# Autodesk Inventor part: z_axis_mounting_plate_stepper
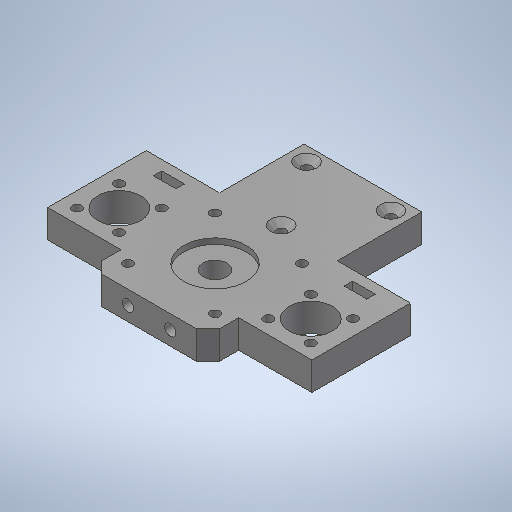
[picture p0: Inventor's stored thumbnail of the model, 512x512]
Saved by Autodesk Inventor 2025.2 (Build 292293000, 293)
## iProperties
Created: 2025-04
Part Number: z_axis_mounting_plate_stepper
Material: 1.0037 S235JR
Document SubType Name: Modeling
Designer: BennF
Density: 7.85 g/cm^3
Appearance: Stahl
Author: BennF
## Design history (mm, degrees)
sketch "Sketch2"
  geometry: L1 (20.9, 75.9)-(-20.9, 75.9); L2 (-20.9, 75.9)-(-20.9, 35.9); L3 (-20.9, 35.9)-(-46.9, 35.9); L4 (-46.9, 35.9)-(-46.9, 10.9); L5 (46.9, 10.9)-(46.9, 35.9); L6 (46.9, 35.9)-(20.9, 35.9); L7 (20.9, 35.9)-(20.9, 75.9); L8 (-20.9, 10.9)-(-20.9, 0); L9 (-20.9, 0)-(20.9, 0); L10 (20.9, 0)-(20.9, 10.9); L11 (-46.9, 10.9)-(-20.9, 10.9); L12 (20.9, 10.9)-(46.9, 10.9); 4 further points
  constraints: 25 end point, 11 perpendicular, 3 midpoint, 2 point on line, 2 vertical alignment, 1 coincident, 1 collinear, 1 horizontal, 1 horizontal alignment, 1 vertical
  dimensions: "d0" = 41.8 distance of L1.start L1.end; "d3" = 93.8 distance of L4.end L5.start (computed from d0); "d34" = 40 distance of L6.end L1.start; "d35" = 10.9 distance of L9.end L10.end; "d36" = 52.5 distance from line of point (46.9, 23.4) L1 (derived); "d37" = 25 distance of L3.end L4.end
extrude "Extrusion1" new body sketch "Sketch2" distance "d4" = 10; taper "d5" = 0 deg
sketch "Sketch3"
  geometry: L1 (-15.5, 38.9)-(15.5, 38.9); L2 (15.5, 38.9)-(15.5, 7.9); L3 (15.5, 7.9)-(-15.5, 7.9); L4 (-15.5, 7.9)-(-15.5, 38.9); L5 (46.9, 35.9)-(46.9, 10.9) reference; 6 further points
  constraints: 8 end point, 3 horizontal alignment, 3 midpoint, 2 parallel, 2 perpendicular, 2 vertical alignment, 1 horizontal
  dimensions: "d13" = 31 distance of L1.start L1.end
hole "Hole1" sketch "Sketch3" at (-15.5, 7.9), (-15.5, 38.9), (15.5, 38.9), (15.5, 7.9) diameter "d6" = 3.4; stored, may be unused: countersink angle "d10" = 90 deg, drill point angle "d12" = 118 deg; dims "d7" = 6, "d8" = 7.5, "d9" = 2, "d11" = 8
sketch "Sketch4"
  geometry: L1 (46.9, -5)-(46.9, 5); L2 (35.8, 5)-(35.8, 3); L3 (35.8, 3)-(42.65, 3); L4 (42.65, 3)-(42.65, -5); L5 (67.8, 5)-(26, 5) reference; L6 (67.8, -5)-(26, -5) reference
  constraints: 8 end point, 2 midpoint, 2 perpendicular, 2 point on line, 1 vertical
  dimensions: "d16" = 22.2 diameter of L2 L1; "d17" = 8.5 diameter of L4 L1; "d18" = 2 distance of L2.start L2.end
revolve "Revolution1" sketch "Sketch4" stored, may be unused: angle "d19" = 360 deg
sketch "Sketch5"
  geometry: L1 (-15, 70.9)-(15, 70.9); L2 (20.9, 75.9)-(-20.9, 75.9) reference; 4 further points
  constraints: 2 end point, 2 midpoint, 2 vertical alignment, 1 horizontal, 1 horizontal alignment
  dimensions: "d27" = 30 distance of L1.start L1.end; "d28" = 24 distance from line of point (0, 46.9) L1; "d29" = 5 distance between parallel lines of L2 L1
hole "Hole2" sketch "Sketch5" at (-15, 70.9), (15, 70.9), (0, 46.9) diameter "d20" = 3.4; stored, may be unused: countersink angle "d24" = 90 deg, drill point angle "d26" = 118 deg; dims "d21" = 6, "d22" = 7.5, "d23" = 2, "d25" = 8
sketch "Sketch6"
  geometry: L1 (-34, 23.4)-(34, 23.4); C1 r 7.65 at (-34, 23.4); C2 r 7.65 at (34, 23.4); C3 r 4.25 at (0, 23.4) reference; 5 further points; 1 other entity
  constraints: 2 centre point, 2 end point, 1 coincident, 1 equal radius, 1 horizontal, 1 horizontal alignment, 1 midpoint, 1 vertical alignment, 2 other
  dimensions: "d30" = 68 distance of L1.start L1.end; "d31" = 15.3 diameter of C2
extrude "Extrusion2" cut sketch "Sketch6" extent not by distance; stored distance "d32" = 0; taper "d33" = 0 deg
chamfer "Chamfer1" distance "d38" = 4; stored, may be unused: second distance "d39" = 2, angle "d40" = 45 deg
sketch "Sketch7"
  geometry: L1 (-41.513, 30.913)-(-26.487, 15.887); L2 (-41.513, 15.887)-(-26.487, 30.913); C1 r 7.65 at (-34, 23.4) reference; C2 r 7.65 at (34, 23.4) reference; A1 r 10.625 centre (-34, 23.4) between (-41.513, 30.913) and (-26.487, 30.913); A2 r 10.625 centre (34, 23.4) between (26.487, 30.913) and (41.513, 30.913); 4 further points
  constraints: 10 point on circle, 6 horizontal alignment, 4 end point, 2 centre point, 2 coincident, 2 midpoint, 2 vertical alignment, 1 equal radius, 1 perpendicular
  dimensions: "d48" = 21.25 diameter of A1
hole "Hole3" sketch "Sketch7" at (-41.513, 30.913), (-41.513, 15.887), (-26.487, 15.887), (-26.487, 30.913), (26.487, 30.913), (26.487, 15.887), (41.513, 15.887), (41.513, 30.913) diameter "d41" = 3.4; stored, may be unused: countersink angle "d45" = 90 deg, drill point angle "d47" = 118 deg; dims "d42" = 6, "d43" = 7.5, "d44" = 2, "d46" = 8
sketch "Sketch8"
  geometry: L1 (-46.9, 10.9)-(-46.9, 35.9) reference; L2 (-46.9, 35.9)-(-46.9, 45.9); L3 (-46.9, 45.9)-(-20.9, 45.9); L4 (-20.9, 35.9)-(-20.9, 75.9) reference; L5 (46.9, 35.9)-(46.9, 10.9) reference; L6 (46.9, 35.9)-(46.9, 45.9); L7 (46.9, 45.9)-(20.9, 45.9); L8 (20.9, 75.9)-(20.9, 35.9) reference; L9 (20.9, 35.9)-(46.9, 35.9) reference; L10 (-46.9, 35.9)-(-20.9, 35.9) reference; L11 (-37.9, 42.4)-(-29.9, 42.4); L12 (-29.9, 42.4)-(-29.9, 39.4); L13 (-29.9, 39.4)-(-37.9, 39.4); L14 (-37.9, 39.4)-(-37.9, 42.4); L15 (29.9, 42.4)-(37.9, 42.4); L16 (37.9, 42.4)-(37.9, 39.4); L17 (37.9, 39.4)-(29.9, 39.4); L18 (29.9, 39.4)-(29.9, 42.4); 9 further points
  constraints: 24 end point, 8 midpoint, 4 parallel, 4 point on line, 3 horizontal, 3 perpendicular, 2 collinear, 2 horizontal alignment, 2 vertical, 2 vertical alignment
  dimensions: "d49" = 10 distance of L1.end L2.end; "d60" = 8 distance of L11.start L11.end; "d61" = 3 distance of L13.end L11.start
extrude "Extrusion3" join sketch "Sketch8" stored distance "d50" = 10; taper "d51" = 0 deg
sketch "Sketch9"
  geometry: L1 (9.4, 5)-(24.4, 5); L2 (0, 0)-(33.8, 0) reference; L3 (-4, 10)-(-4, 0) reference; 4 further points
  constraints: 3 midpoint, 2 end point, 2 horizontal alignment, 1 horizontal, 1 vertical alignment
  dimensions: "d59" = 15 distance of L1.start L1.end
hole "Hole4" sketch "Sketch9" at (9.4, 5), (24.4, 5) diameter "d52" = 3; stored, may be unused: countersink angle "d56" = 90 deg, drill point angle "d58" = 0 deg; dims "d53" = 8, "d54" = 4, "d55" = 6.7, "d57" = 9
body "Solid1"
workplane "Work Plane1"
other parameters: "d1" = 75
